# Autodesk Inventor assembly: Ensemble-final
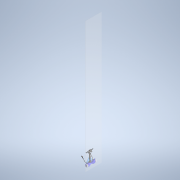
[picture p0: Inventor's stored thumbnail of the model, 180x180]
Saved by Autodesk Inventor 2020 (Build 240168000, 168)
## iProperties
Created: 2022-10
Part Number: Ensemble-final
Document SubType Name: Assembly
Designer: bruno
Author: bruno
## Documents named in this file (6)
- C:\Users\bruno\Documents\1-Cours-2022-23\1SI\2. Cinématique\Hoverboard\Inventor-Hoverkart\Ensemble-final.iam
- C:\Users\bruno\Documents\1-Cours-2022-23\1SI\2. Cinématique\Hoverboard\Inventor-Hoverkart\Ensemble-final-corps.iam
- C:\Users\bruno\Documents\1-Cours-2022-23\1SI\2. Cinématique\Hoverboard\Inventor-Hoverkart\Wheel.ipt
- C:\Users\bruno\Documents\1-Cours-2022-23\1SI\2. Cinématique\Hoverboard\Inventor-Hoverkart\Sol.ipt
- C:\Users\bruno\Documents\1-Cours-2022-23\1SI\2. Cinématique\Hoverboard\Inventor-Hoverkart\Roue-avant.ipt
- C:\Users\bruno\Documents\1-Cours-2022-23\1SI\2. Cinématique\Hoverboard\Inventor-Hoverkart\Wheel-2.ipt
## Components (5 placed, 5 different names)
1. Ensemble-final-corps:1 [sub-assembly] — Logement:2, Logement:3, Logement:4
2. Wheel:2 — Logement:2
3. Sol:1 — Tangente:1
4. Roue-avant:1 — Logement:3
5. Wheel-2:1 — Logement:4, Tangente:1
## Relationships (4: Insert 3, Tangent 1)
- Logement:2 [Insert]: Ensemble-final-corps:1 ↔ Wheel:2
- Logement:3 [Insert]: Ensemble-final-corps:1 ↔ Roue-avant:1
- Logement:4 [Insert]: Ensemble-final-corps:1 ↔ Wheel-2:1
- Tangente:1: Sol:1 ↔ Wheel-2:1
